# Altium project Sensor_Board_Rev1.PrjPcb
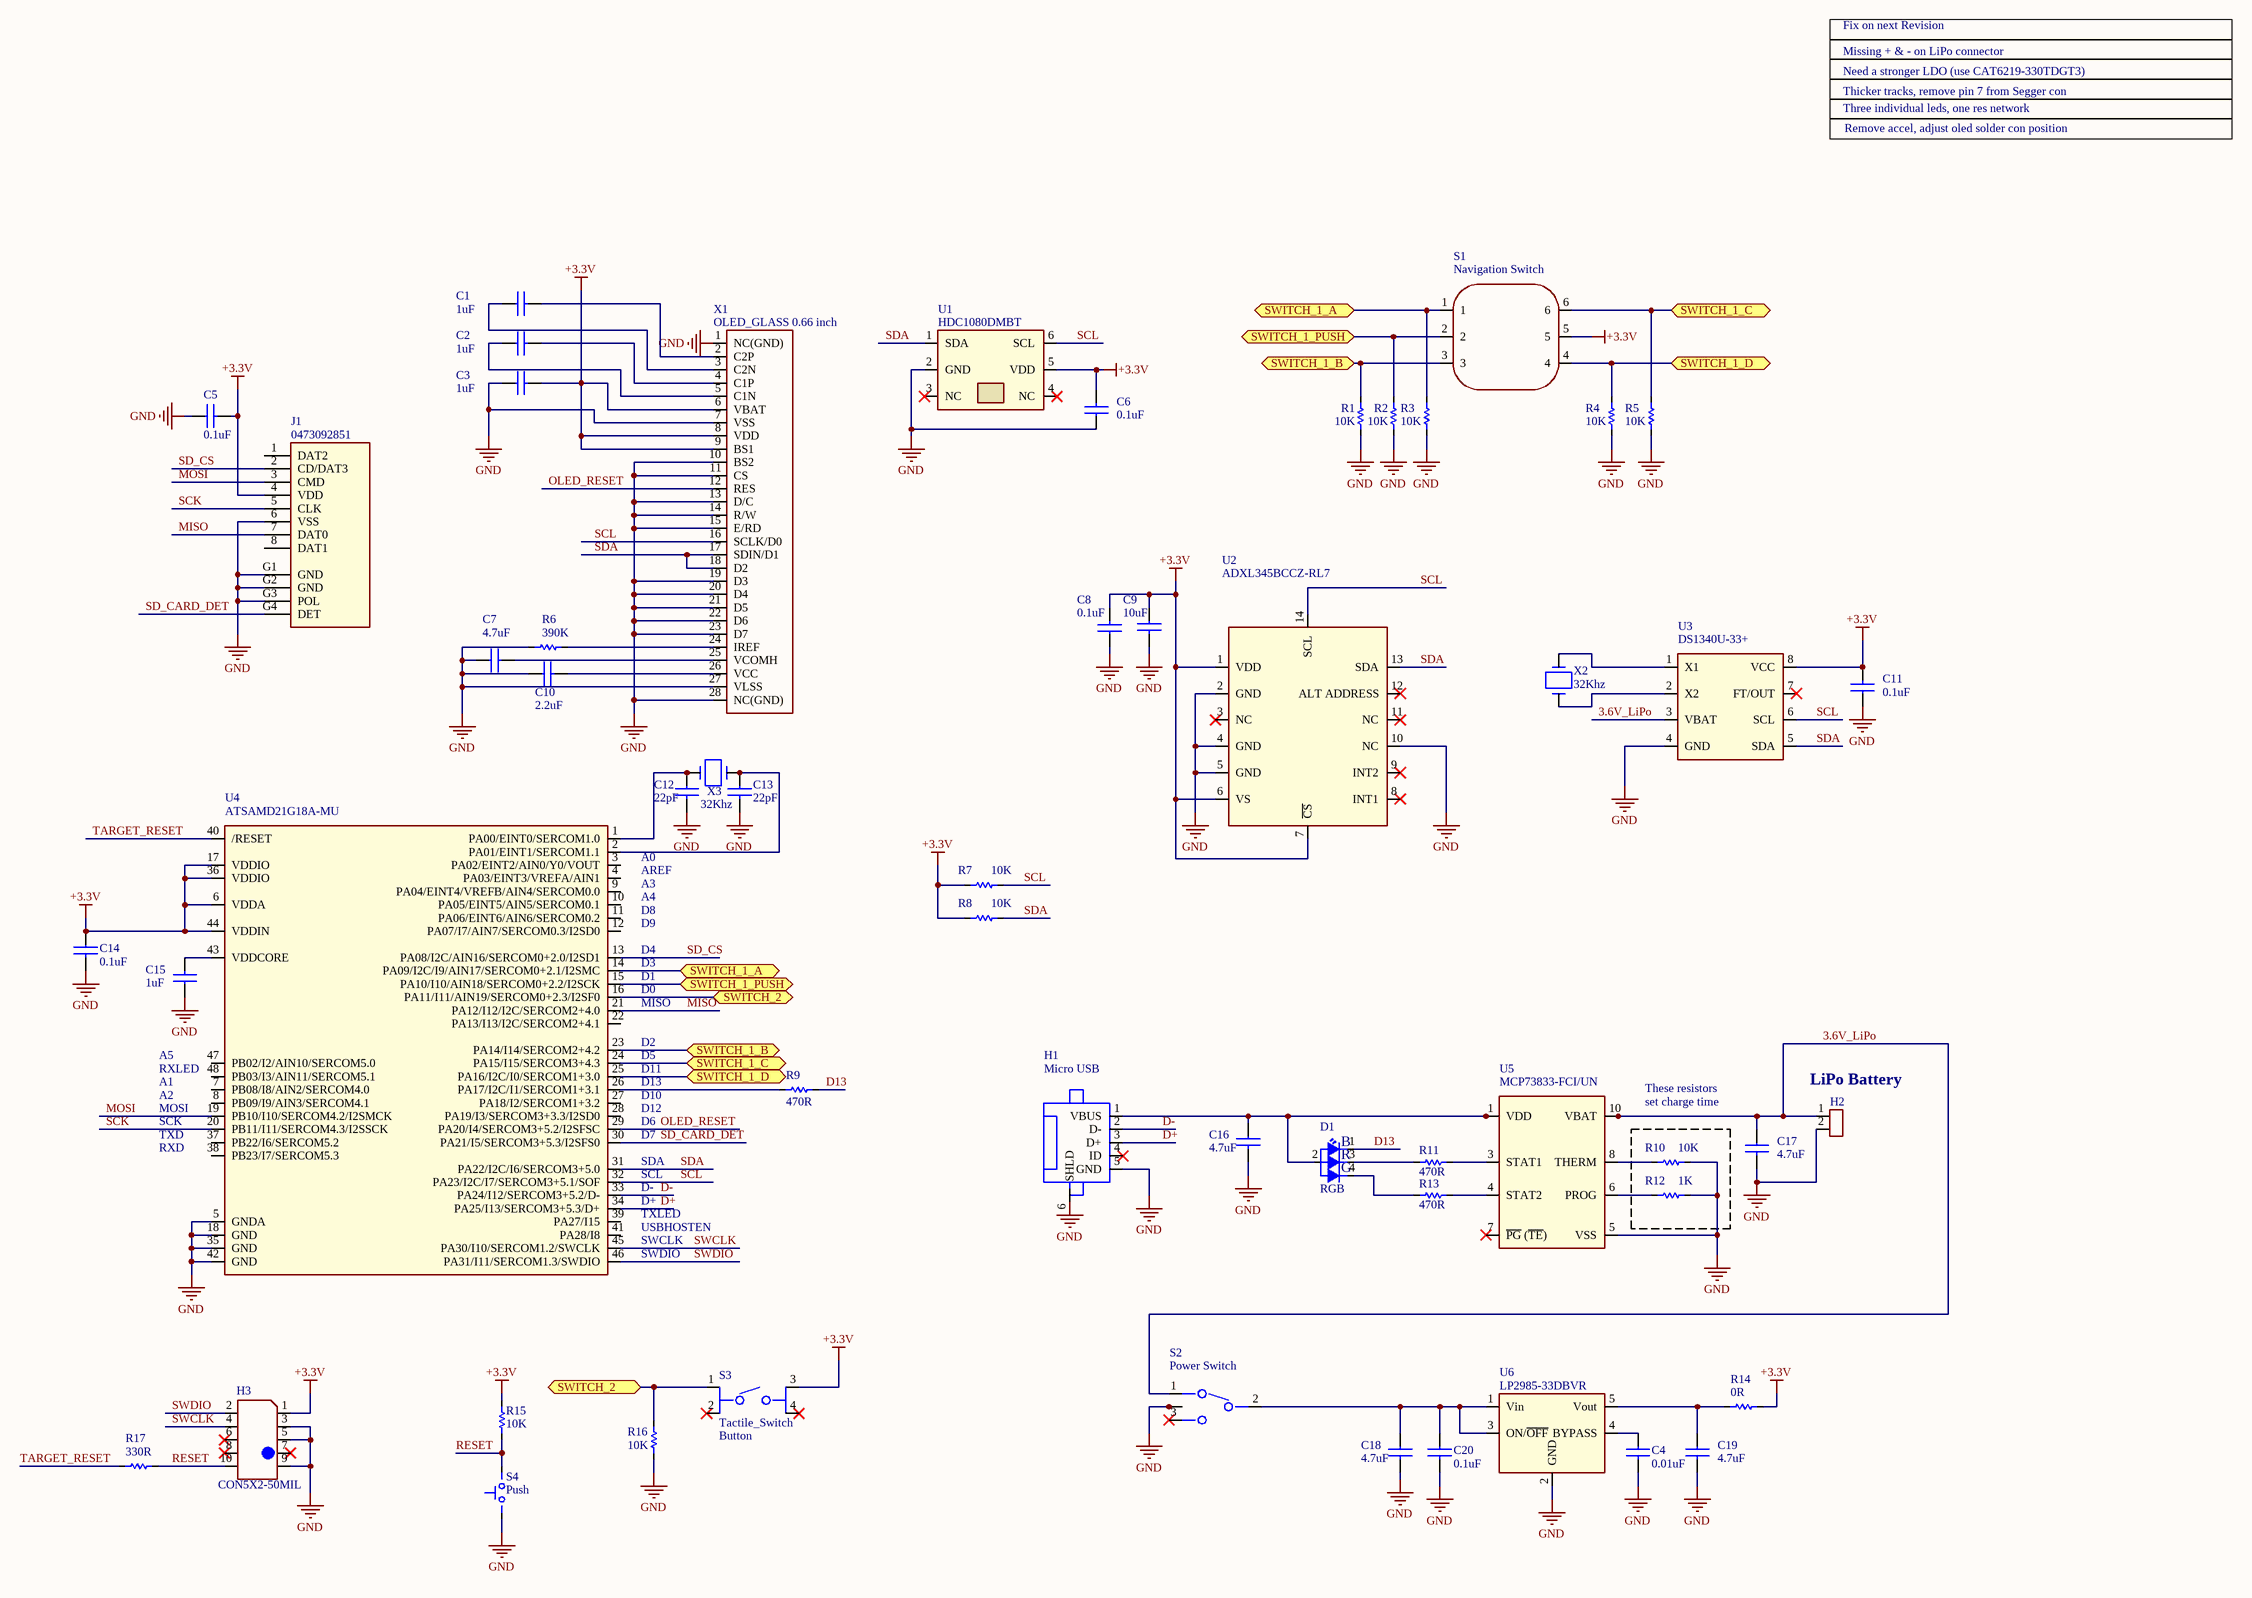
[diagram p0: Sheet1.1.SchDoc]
1 sheet, 55 parts. Net scope: flat (ports and power ports of the same name join across sheets).
Board file: PCB_Rev1.PcbDoc

## Sheet Sheet1.1.SchDoc
size C

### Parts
C1  1uF  [CAPC1608X09L]
C2  1uF  [CAPC1608X09L]
C3  1uF  [CAPC1608X09L]
C4  0.01uF  [CAPC1608X09L]
C5  0.1uF  [CAPC1608X09L]
C6  0.1uF  [CAPC1608X09L]
C7  4.7uF  [CAPC1608X09L]
C8  0.1uF  [CAPC1608X09L]
C9  10uF  [CAPC3216X160L]
C10  2.2uF  [CAPC1608X09L]
C11  0.1uF  [CAPC1608X09L]
C12  22pF  [CAPC1608X09L]
C13  22pF  [CAPC1608X09L]
C14  0.1uF  [CAPC1608X09L]
C15  1uF  [CAPC1608X09L]
C16  4.7uF  [CAPC3216X160L]
C17  4.7uF  [CAPC3216X160L]
C18  4.7uF  [CAPC3216X160L]
C19  4.7uF  [CAPC3216X160L]
C20  0.1uF  [CAPC1608X09L]
D1  RGB  [HSMF-C115]
H1  Micro USB  [1981584-1]
H2  CON2  [HDR1X2-EMPTY]  (value not drawn)
H3  CON5X2-50MIL  [HDR5X2-50MIL-SMT]
J1  0473092851  [0473092851]
R1  10K  [RESC1608X06L]
R2  10K  [RESC1608X06L]
R3  10K  [RESC1608X06L]
R4  10K  [RESC1608X06L]
R5  10K  [RESC1608X06L]
R6  390K  [RESC1608X06L]
R7  10K  [RESC1608X06L]
R8  10K  [RESC1608X06L]
R9  470R  [RESC1608X06L]
R10  10K  [RESC1608X06L]
R11  470R  [RESC1608X06L]
R12  1K  [RESC1608X06L]
R13  470R  [RESC1608X06L]
R14  0R  [RESC1608X06L]
R15  10K  [RESC1608X06L]
R16  10K  [RESC1608X06L]
R17  330R  [RESC1608X06L]
S1  Navigation Switch  [NAVIGATION - DX]
S2  (no value)  [SLIDE_SWITCH_DX]
S3  Tactile_Switch  value Button  [FSM6JSMA]
S4  Push  [TL1015AF160QG]
U1  HDC1080DMBT  [S-PWSON-N6]
U2  ADXL345BCCZ-RL7  [LGA80P300X500X100-14N]
U3  DS1340U-33+  [TSOP65P490X110-8N]
U4  ATSAMD21G18A-MU  [QFN48]
U5  MCP73833-FCI/UN  [TSSOP50P490X110-10N]
U6  LP2985-33DBVR  [SOT95P280X144-5N]
X1  OLED_GLASS 0.66 inch  [OLED_GLASS 0.66 INCH]
X2  value 32Khz  [ECS-.327-12.5-34B]  (hidden comment: ECS-.327-12.5-34B)
X3  value 32Khz  [ECS-.327-12.5-34B]  (hidden comment: ECS-.327-12.5-34B)

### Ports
SWITCH_1_A (bidir), SWITCH_1_B (bidir), SWITCH_1_C (bidir), SWITCH_1_D (bidir), SWITCH_1_PUSH (bidir), SWITCH_2 (bidir)

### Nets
+3.3V: C3.2 C5.2 C6.2 C8.2 C9.1 C11.2 C14.1 H3.1 J1.4(VDD) R7.2 R8.2 R14.2 R15.2 S1.5 S3.3 U1.5(VDD) U2.1(VDD) U2.6(VS) U2.7(~{CS}) U3.8(VCC) U4.6(VDDA) U4.17(VDDIO) U4.36(VDDIO) U4.44(VDDIN) X1.6(VBAT) X1.8(VDD) X1.9(BS1)
GND: C3.1 C4.2 C5.1 C6.1 C7.1 C8.1 C9.2 C10.1 C11.1 C12.2 C13.2 C14.2 C15.1 C16.2 C17.2 C18.2 C19.2 C20.2 H1.5(GND) H1.6(SHLD) H2.2 H3.3 H3.5 H3.9 J1.6(VSS) J1.G1(GND) J1.G2(GND) J1.G3(POL) R1.1 R2.1 R3.1 R4.1 R5.1 R6.1 R10.1 R12.1 R16.1 S2.4(GND) S2.5(GND) S4.1(A) U1.2(GND) U2.2(GND) U2.4(GND) U2.5(GND) U2.10(NC) U3.4(GND) U4.5(GNDA) U4.18(GND) U4.35(GND) U4.42(GND) U5.5(VSS) U6.2(GND) X1.1(NC(GND)) X1.7(VSS) X1.10(BS2) X1.11(CS) X1.13(D/C) X1.14(R/W) X1.15(E/RD) X1.19(D3) X1.20(D4) X1.21(D5) X1.22(D6) X1.23(D7) X1.27(VLSS) X1.28(NC(GND))
3.6V_LiPo: C17.1 H2.1 S2.1(A) U3.3(VBAT) U5.9(VBAT) U5.10(VBAT)
D13: D1.1 R9.2
D+: H1.3(D+) U4.34(PA25/I13/SERCOM3+5.3/D+)
D-: H1.2(D-) U4.33(PA24/I12/SERCOM3+5.2/D-)
MISO: J1.7(DAT0) U4.21(PA12/I12/I2C/SERCOM2+4.0)
MOSI: J1.3(CMD) U4.19(PB10/I10/SERCOM4.2/I2SMCK)
OLED_RESET: U4.29(PA20/I4/SERCOM3+5.2/I2SFSC) X1.12(RES)
RESET: H3.10 R15.1 R17.2 S4.2(B)
SCK: J1.5(CLK) U4.20(PB11/I11/SERCOM4.3/I2SSCK)
SCL: R7.1 U1.6(SCL) U2.14(SCL) U3.6(SCL) U4.32(PA23/I2C/I7/SERCOM3+5.1/SOF) X1.16(SCLK/D0)
SD_CARD_DET: J1.G4(DET) U4.30(PA21/I5/SERCOM3+5.3/I2SFS0)
SD_CS: J1.2(CD/DAT3) U4.13(PA08/I2C/AIN16/SERCOM0+2.0/I2SD1)
SDA: R8.1 U1.1(SDA) U2.13(SDA) U3.5(SDA) U4.31(PA22/I2C/I6/SERCOM3+5.0) X1.17(SDIN/D1) X1.18(D2)
SWCLK: H3.4 U4.45(PA30/I10/SERCOM1.2/SWCLK)
SWDIO: H3.2 U4.46(PA31/I11/SERCOM1.3/SWDIO)
TARGET_RESET: R17.1 U4.40(/RESET)
NetC1_1: C1.1 X1.3(C2N)
NetC1_2: C1.2 X1.2(C2P)
NetC2_1: C2.1 X1.5(C1N)
NetC2_2: C2.2 X1.4(C1P)
NetC4_1: C4.1 U6.4(BYPASS)
NetC7_2: C7.2 X1.25(VCOMH)
NetC10_2: C10.2 X1.26(VCC)
NetC12_1: C12.1 U4.1(PA00/EINT0/SERCOM1.0) X3.1
NetC13_1: C13.1 U4.2(PA01/EINT1/SERCOM1.1) X3.2
NetC15_2: C15.2 U4.43(VDDCORE)
NetC16_1: C16.1 D1.2 H1.1(VBUS) U5.1(VDD) U5.2(VDD)
NetC18_1: C18.1 C20.1 S2.2(Middle) U6.1(Vin) U6.3(ON/~{OFF})
NetC19_1: C19.1 R14.1 U6.5(Vout)
NetD1_3: D1.3 R11.2
NetD1_4: D1.4 R13.2
NetR1_2: R1.2 S1.3 U4.23(PA14/I14/SERCOM2+4.2) ; port SWITCH_1_B
NetR2_2: R2.2 S1.2 U4.15(PA10/I10/AIN18/SERCOM0+2.2/I2SCK) ; port SWITCH_1_PUSH
NetR3_2: R3.2 S1.1 U4.14(PA09/I2C/I9/AIN17/SERCOM0+2.1/I2SMC) ; port SWITCH_1_A
NetR4_2: R4.2 S1.4 U4.25(PA16/I2C/I0/SERCOM1+3.0) ; port SWITCH_1_D
NetR5_2: R5.2 S1.6 U4.24(PA15/I15/SERCOM3+4.3) ; port SWITCH_1_C
NetR6_2: R6.2 X1.24(IREF)
NetR9_1: R9.1 U4.26(PA17/I2C/I1/SERCOM1+3.1)
NetR10_2: R10.2 U5.8(THERM)
NetR11_1: R11.1 U5.3(STAT1)
NetR12_2: R12.2 U5.6(PROG)
NetR13_1: R13.1 U5.4(STAT2)
NetR16_2: R16.2 S3.1 U4.16(PA11/I11/AIN19/SERCOM0+2.3/I2SF0) ; port SWITCH_2
NetU3_1: U3.1(X1) X2.2
NetU3_2: U3.2(X2) X2.1

Not connected (* = marked no-connect by the designer): H1 4(ID)*; H3 6* 7* 8*; J1 1(DAT2) 8(DAT1); S2 3(B)*; S3 2* 4*; U1 3(NC)* 4(NC)*; U2 3(NC)* 8(INT1)* 9(INT2)* 11(NC)* 12(ALT_ADDRESS)*; U3 7(FT/OUT)*; U4 3(PA02/EINT2/AIN0/Y0/VOUT) 4(PA03/EINT3/VREFA/AIN1) 7(PB08/I8/AIN2/SERCOM4.0) 8(PB09/I9/AIN3/SERCOM4.1) 9(PA04/EINT4/VREFB/AIN4/SERCOM0.0) 10(PA05/EINT5/AIN5/SERCOM0.1) 11(PA06/EINT6/AIN6/SERCOM0.2) 12(PA07/I7/AIN7/SERCOM0.3/I2SD0) 22(PA13/I13/I2C/SERCOM2+4.1) 27(PA18/I2/SERCOM1+3.2) 28(PA19/I3/SERCOM3+3.3/I2SD0) 37(PB22/I6/SERCOM5.2) 38(PB23/I7/SERCOM5.3) 39(PA27/I15) 41(PA28/I8) 47(PB02/I2/AIN10/SERCOM5.0) 48(PB03/I3/AIN11/SERCOM5.1); U5 7(~{PG}_(~{TE}))*

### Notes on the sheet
- Missing + & - on LiPo connector
- Fix on next Revision
- Need a stronger LDO (use CAT6219-330TDGT3)
- Thicker tracks, remove pin 7 from Segger con
- Three individual leds, one res network
- Remove accel, adjust oled solder con position
- These resistors
- set charge time
- (near H2) LiPo Battery
- (near S2) Power Switch

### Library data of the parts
C1-C3 C15 = CAP_0603: CAP, 1uF, 0603
C4 = CAP_0603: CAP, 0.01uF, 0603
C5 C6 C8 C11 C14 C20 = CAP_0603: CAP, 0.1uF, 0603
C7 = CAP_0603: CAP, 4.7uF, 0603
C9 = CAP_1206: CAP, 10uF, 1206
C10 = CAP_0603: CAP, 2.2uF, 0603
C12 C13 = CAP_0603: CAP, 22pF, 0603
C16-C19 = CAP_1206: CAP, 4.7uF, 1206
D1 = HSMF-C115: LED,RGB,10mA,SMD,R/A,RoHS; Manufacturer: AVAGO; Vendor: Digi-Key
H1 = 1981584-1: CONN RCPT MICRO USB TYPE AB; Manufacturer: TE Connectivity; Vendor: Digi-Key
H2 = CON2-EMPTY_PAD: EMPTY SOLDER 2POS
H3 = CON5X2_50mil: JTAG CONN HEADER 5X2POS 50mil" PADS
J1 = 0473092851: 9 (8 + 1) microSD SMT, Right Angle; Manufacturer: Molex; Vendor: Digi-Key
R1-R5 R7 R8 R10 R15 R16 = RES_0603: RES, 10K, 0603
R6 = RES_0603: RES, 390K, 0603
R9 R11-R13 = RES_0603: RES, 470R, 0603
R14 = RES_0603: RES, 0R, 0603
R17 = RES_0603: RES, 330R, 0603
S1 = DX_NAV: DX_Navigation Switch; PartNumber: 122745; Value: DX_Navigation_Switch; Vendor: DX.com
S2 = DX_SLIDE_SWITCH: DX_SWITCH SLIDE SPDT R/A; PartNumber: 122531; Vendor: DX.com
S3 = FSM6JSMA: SWITCH TACTILE SPST-NO 0.05A 12V; Manufacturer: TE Connectivity; Vendor: Digi-Key
S4 = DX_MINI_TACT_SWITCH: DX_SWITCH TACTILE; PartNumber: 122514; Value: Mini PushButton; Vendor: DX.com
U1 = HDC1080DMBT: Humidity/Temperature Sensor; Manufacturer: Texas Instruments; Vendor: Digi-Key
U2 = ADXL345BCCZ-RL7: IC ACCEL SPI/I2C 3AX 14LGA; Manufacturer: Analog Devices; Vendor: Digi-Key
U3 = DS1340U-33+: IC RTC SERIAL 512K 8-TSSOP; Manufacturer: Maxim; Vendor: Digi-Key
U4 = ATSAMD21G18A-MU: IC MCU 32BIT 256KB FLASH 48QFN; Manufacturer: Atmel; Vendor: Digi-Key
U5 = MCP73833-FCI/UN: IC LI-ION/LI-POLY CTRLR 10MSOP; Manufacturer: Microchip; Vendor: Digi-Key
U6 = LP2985-33DBVR: IC REG LDO 3.3V .15A SOT23-5; Manufacturer: Texas Instruments; Vendor: Digikey
X1 = OLED_GLASS 0.66 inch: 0.66 inch OLED_GLASS_Blue; PartNumber: ER-OLED0.66-1B; Vendor: Buy-Display; Vendor: BuyDisplay.com
X2 X3 = ECS-.327-12.5-34B: CRYSTAL 32.768 KHZ 12.5PF SMD; Manufacturer: ECS; Vendor: Digi-Key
